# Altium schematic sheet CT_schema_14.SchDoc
size 390 x 385 mm
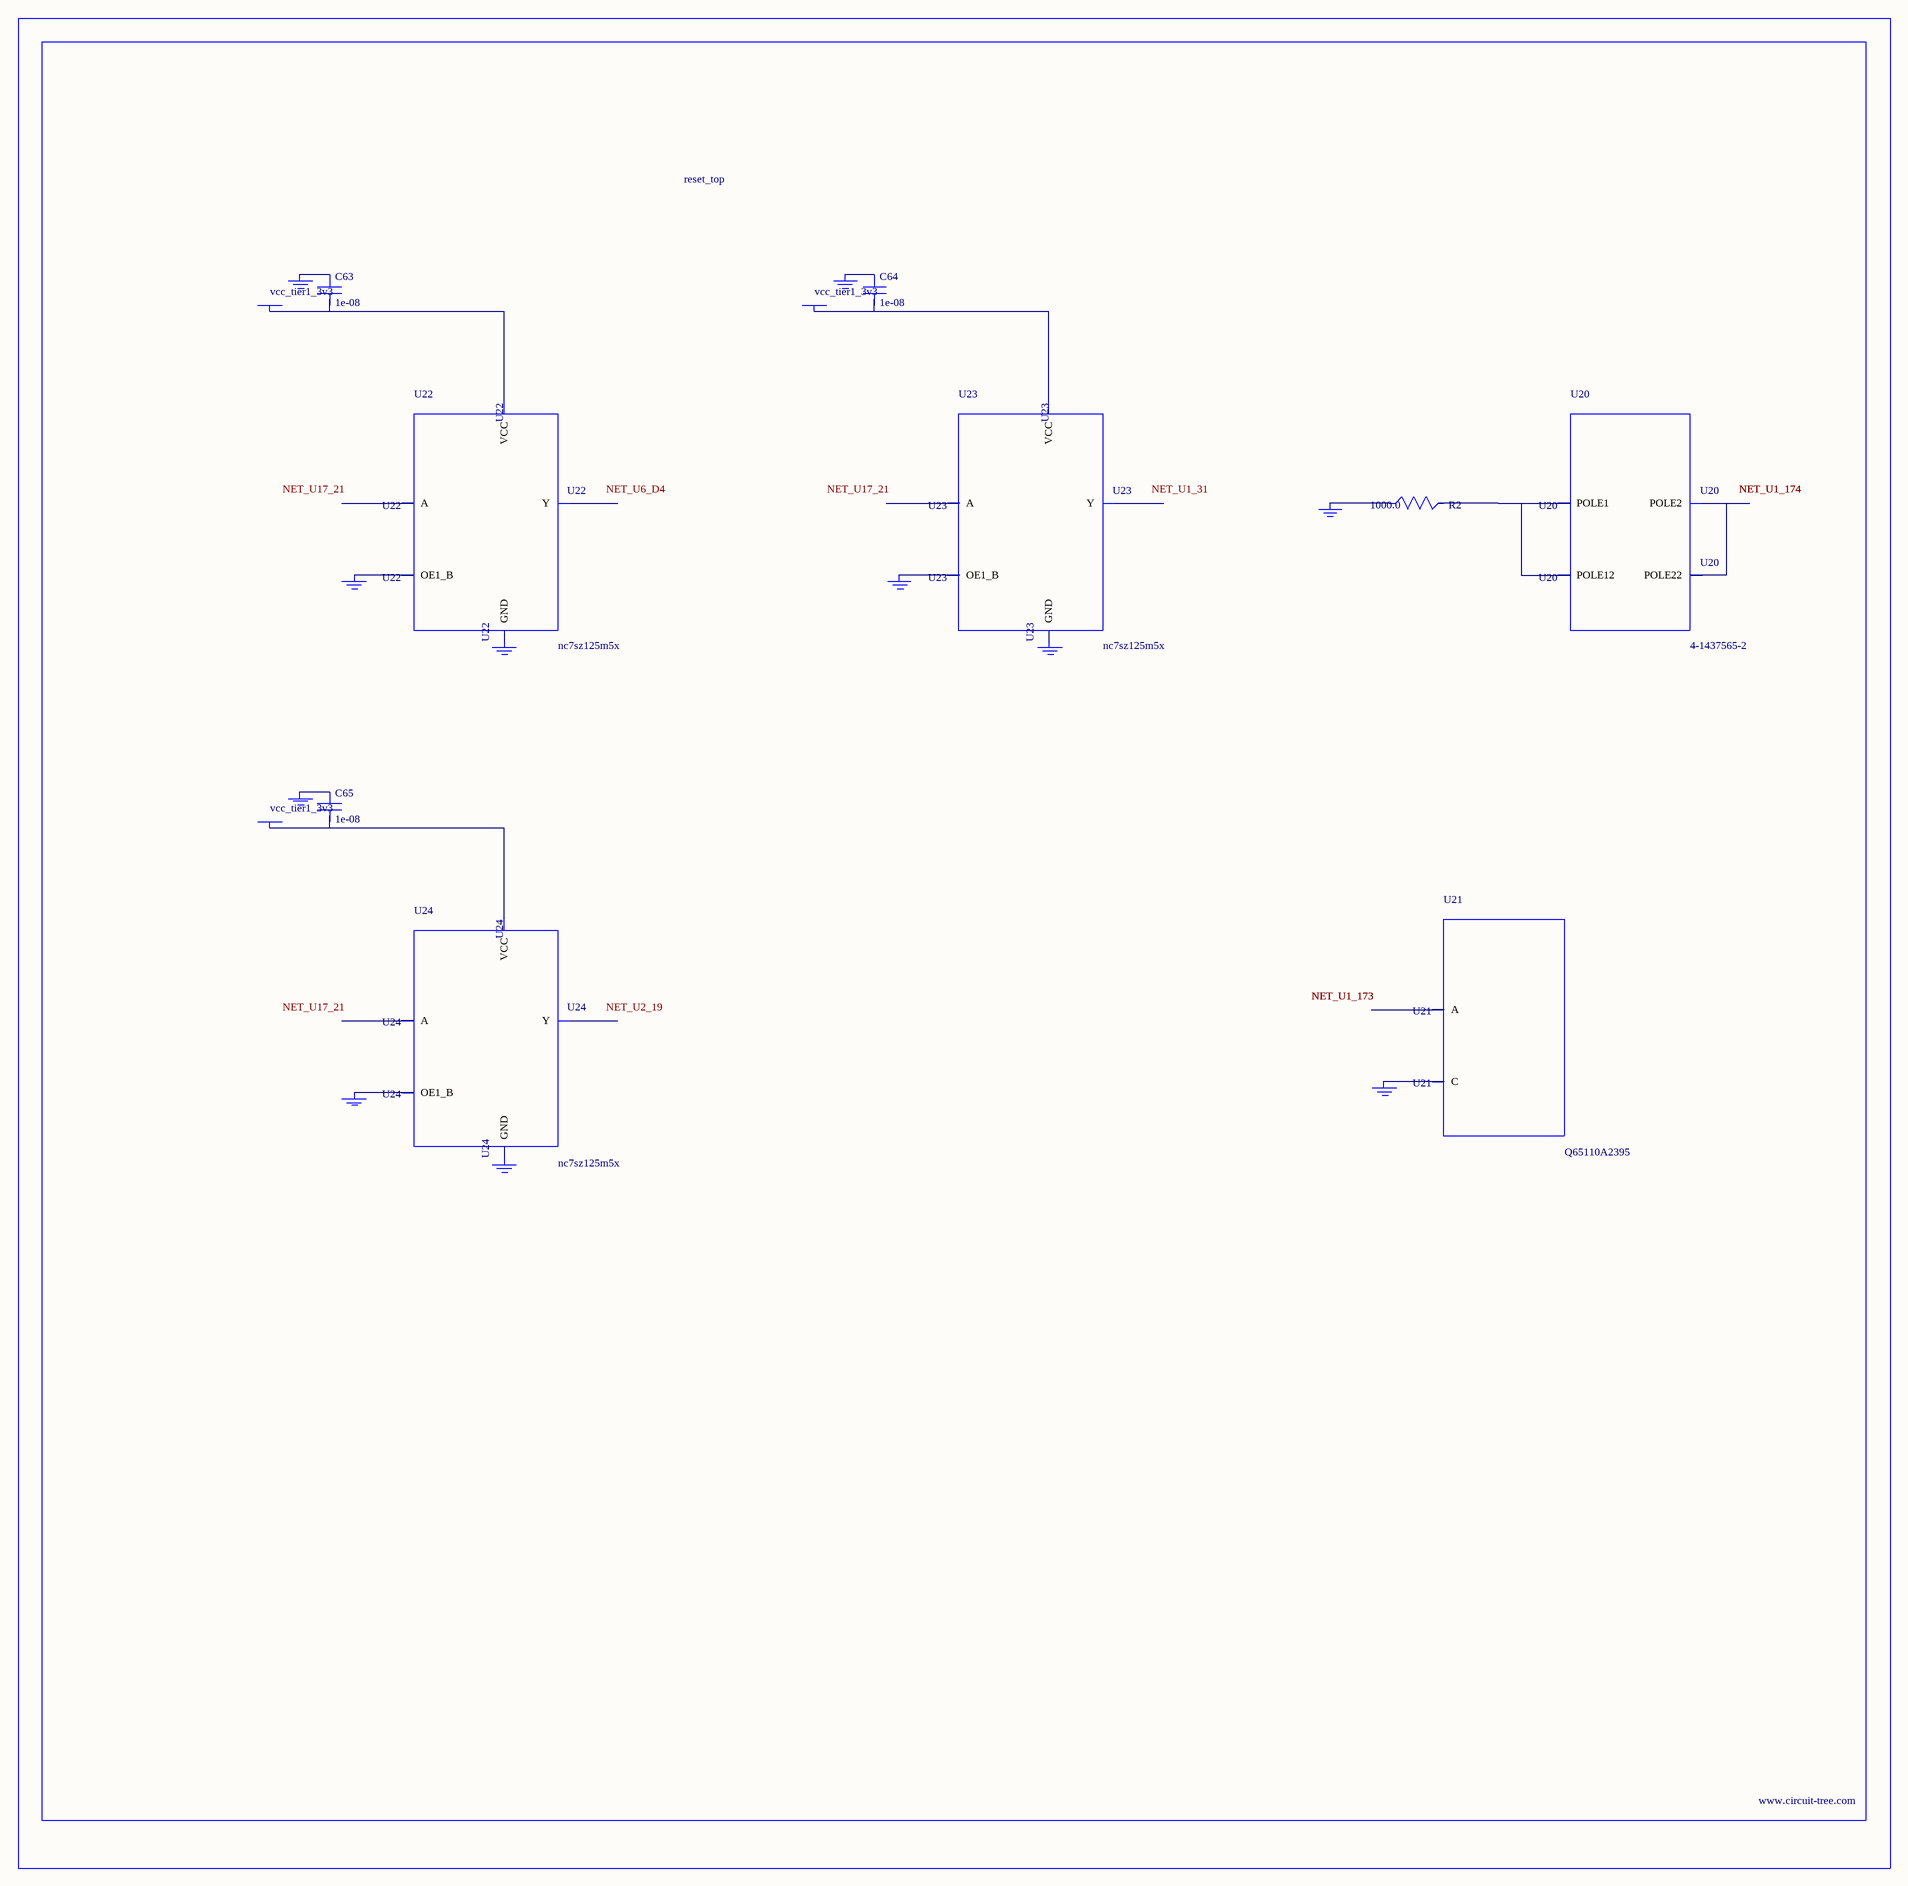
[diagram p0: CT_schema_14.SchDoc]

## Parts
BORDER13  (no value)
C63  1e-08  [C0402]
C64  1e-08  [C0402]
C65  1e-08  [C0402]
GND_INSTANCE_13_0  (no value)
GND_INSTANCE_13_1  (no value)
GND_INSTANCE_13_2  (no value)
GND_INSTANCE_13_3  (no value)
GND_INSTANCE_13_4  (no value)
GND_INSTANCE_13_5  (no value)
GND_INSTANCE_13_6  (no value)
GND_INSTANCE_13_7  (no value)
GND_INSTANCE_13_8  (no value)
GND_INSTANCE_13_9  (no value)
GND_INSTANCE_13_10  (no value)
POWER_INSTANCE_13_0  vcc_tier1_3v3
POWER_INSTANCE_13_1  vcc_tier1_3v3
POWER_INSTANCE_13_2  vcc_tier1_3v3
R2  1000.0  [R0603]
U20  4-1437565-2  [SW_4-1437565-2]
U21  Q65110A2395  [LGM67K-G1J2-24-Z]
U22  nc7sz125m5x  [NC7SZ125M5X]
U23  nc7sz125m5x  [NC7SZ125M5X]
U24  nc7sz125m5x  [NC7SZ125M5X]

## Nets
NetC63_1: C63.1 GND_INSTANCE_13_2.0(GND)
NetC63_2: C63.2 POWER_INSTANCE_13_0.0(PWR) U22.5(VCC)
NetC64_1: C64.1 GND_INSTANCE_13_5.0(GND)
NetC64_2: C64.2 POWER_INSTANCE_13_1.0(PWR) U23.5(VCC)
NetC65_1: C65.1 GND_INSTANCE_13_8.0(GND)
NetC65_2: C65.2 POWER_INSTANCE_13_2.0(PWR) U24.5(VCC)
NetGND_INSTANCE_13_0_0: GND_INSTANCE_13_0.0(GND) R2.1
NetGND_INSTANCE_13_1_0: GND_INSTANCE_13_1.0(GND) U21.C
NetGND_INSTANCE_13_3_0: GND_INSTANCE_13_3.0(GND) U22.1(OE1_B)
NetGND_INSTANCE_13_4_0: GND_INSTANCE_13_4.0(GND) U22.3(GND)
NetGND_INSTANCE_13_6_0: GND_INSTANCE_13_6.0(GND) U23.1(OE1_B)
NetGND_INSTANCE_13_7_0: GND_INSTANCE_13_7.0(GND) U23.3(GND)
NetGND_INSTANCE_13_9_0: GND_INSTANCE_13_9.0(GND) U24.1(OE1_B)
NetGND_INSTANCE_13_10_0: GND_INSTANCE_13_10.0(GND) U24.3(GND)
NetR2_2: R2.2 U20.1(POLE1) U20.2(POLE12)
NetU20_3: U20.3(POLE2) U20.4(POLE22)

Not connected (* = marked no-connect by the designer): U21 A; U22 2(A) 4(Y); U23 2(A) 4(Y); U24 2(A) 4(Y)

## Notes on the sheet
- Labels drawn without touching a wire or pin: NET_U1_31, NET_U2_19, NET_U6_D4, NET_U17_21

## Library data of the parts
BORDER13 = BORDER_PAGE13
C63-C65 = C0402C103K3RAC
GND_INSTANCE_13_0-GND_INSTANCE_13_10 = GND
POWER_INSTANCE_13_0-POWER_INSTANCE_13_2 = PWR
R2 = RC0603JR-071KL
